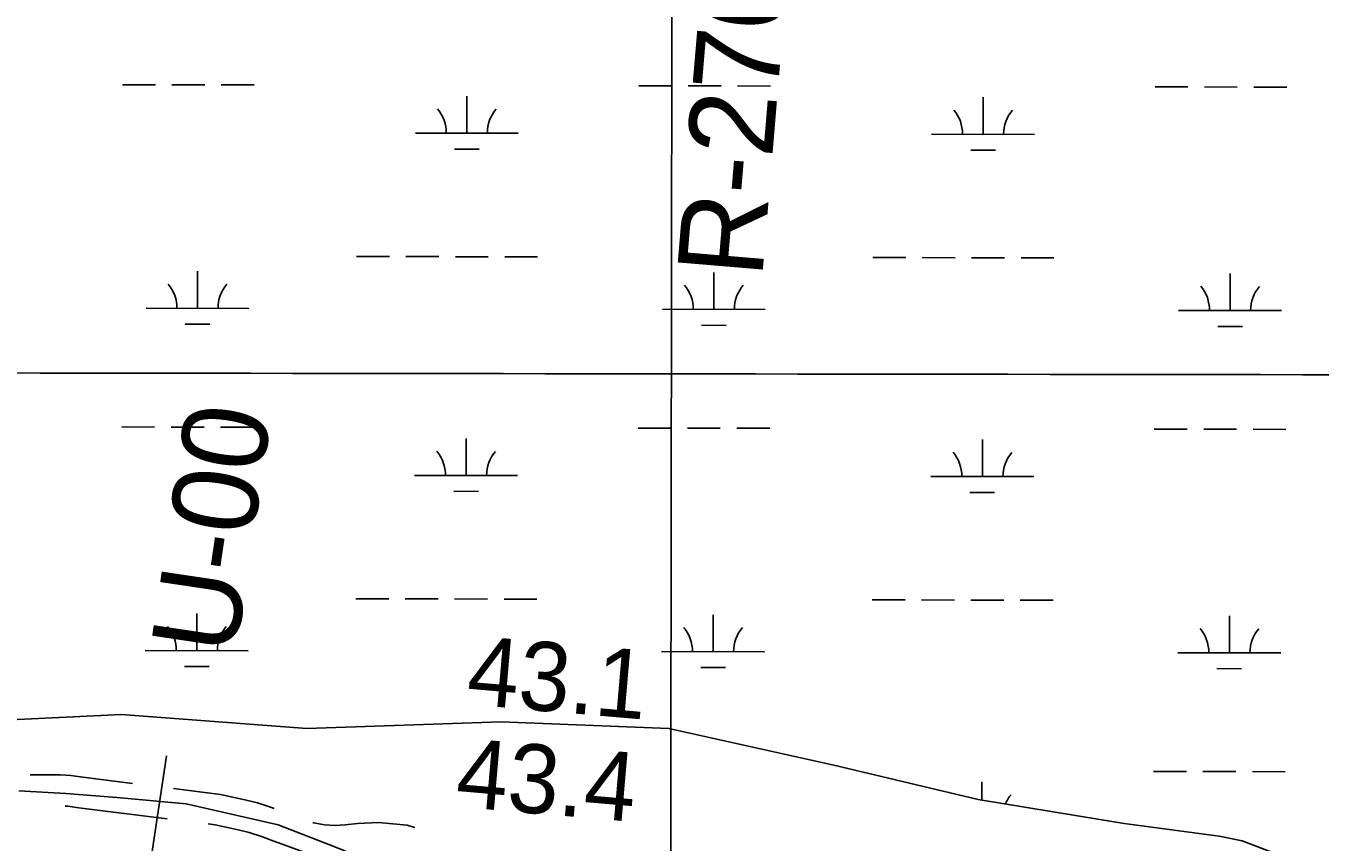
# Model space of a CAD drawing. Extents: x 3219052 to 3256913, y 800770 to 826146.
# Drawn here: x 3233083 to 3234341, y 817838 to 818631 of the extents above; entities that cross this region are included whole.
import ezdxf

# ---------------------------------------------------------------- set-up
doc = ezdxf.new("R2010")
doc.units = 0
for name, color, linetype in [('V-GRID-MAJR', 7, 'Continuous'), ('V-RIVR-RANG', 7, 'Continuous'), ('V-RIVR-RANG-IDEN', 7, 'Continuous'), ('V-ROAD-CNTR', 7, 'Continuous'), ('V-WETL-SWMP', 7, 'Continuous')]:
    doc.layers.add(name, color=color, linetype=linetype)

msp = doc.modelspace()

# ---------------------------------------------------------------- linework, layer by layer
at = {"layer": 'V-GRID-MAJR'}
for points in [[(3233694.758, 806171.2980000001), (3233702.6890000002, 812230.425), (3233710.625, 818292.637), (3233718.561, 824354.887), (3233718.565, 824357.932)], [(3223238.921, 818307.868), (3228474.772, 818299.872), (3233710.625, 818292.637), (3238946.4790000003, 818286.164), (3244182.3340000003, 818280.452), (3249418.1890000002, 818275.502), (3254654.045, 818271.314), (3254654.046, 818271.314)]]:
    msp.add_spline(points, degree=3, dxfattribs=at)
at = {"layer": 'V-RIVR-RANG'}
msp.add_line((3233219.9334, 817921.4696), (3233109.1662, 817189.8066999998), dxfattribs=at)
at = {"layer": 'V-ROAD-CNTR'}
for points in [[(3233186.928440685, 817894.5779960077), (3233138.598091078, 817900.6199709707), (3233126.7553922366, 817902.2062330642), (3233116.7853485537, 817902.7836993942), (3233107.465471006, 817902.962), (3233088.5408772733, 817902.962), (3233087.4304186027, 817902.9536902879)], [(3233076.263810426, 817887.37719786), (3233121.954719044, 817884.6432033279), (3233171.4426200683, 817880.9852106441)], [(3233324.4622326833, 817870.3409500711), (3233321.8827802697, 817871.2554452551), (3233308.3749821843, 817875.7930884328), (3233296.0248369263, 817878.684366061), (3233272.2348375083, 817883.9134939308), (3233226.6189883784, 817889.6161180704)], [(3233220.646218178, 817860.1292795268), (3233134.745908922, 817870.8680290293), (3233123.8926077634, 817872.3217669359), (3233121.4170553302, 817872.4651512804)], [(3233171.4426200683, 817880.9852106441), (3233239.0844847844, 817874.734223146), (3233328.46630602, 817854.3112639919), (3233385.2521924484, 817832.321307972), (3233435.042092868, 817811.8473489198), (3233530.56590182, 817784.111404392), (3233599.983762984, 817772.570427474), (3233839.3082843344, 817719.3975338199), (3233898.8251653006, 817713.3295459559), (3233948.552065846, 817722.858526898), (3234001.823959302, 817725.3345219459), (3234073.093816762, 817719.624533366), (3234135.356692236, 817705.770561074), (3234232.863497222, 817685.1646022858), (3234340.765281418, 817661.7506491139)], [(3233356.016185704, 817827.0294607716), (3233355.416792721, 817827.1315930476), (3233336.977398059, 817833.756292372), (3233324.1808717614, 817838.6111104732), (3233312.0932197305, 817842.8965547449), (3233300.1610178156, 817846.9049115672), (3233289.385163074, 817849.4276339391), (3233267.1431624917, 817854.3165060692), (3233260.3367564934, 817855.1674027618)], [(3233461.211996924, 817851.6729738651), (3233460.05692599, 817852.215786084), (3233453.8880851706, 817853.933947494), (3233425.877738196, 817856.5252657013), (3233419.2603250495, 817856.3603155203), (3233405.5972574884, 817855.5050652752), (3233393.499416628, 817854.2111997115), (3233383.6671431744, 817853.7703696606), (3233373.550651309, 817854.474103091), (3233363.067207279, 817856.2604069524), (3233362.037222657, 817856.630448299)]]:
    msp.add_lwpolyline(points, dxfattribs=at)
at = {"layer": 'V-WETL-SWMP'}
for p, q in [((3233177.005508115, 818573.7098373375), (3233209.0054377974, 818573.6427683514)), ((3233225.0054026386, 818573.6092338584), (3233257.0053323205, 818573.5421648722)), ((3233273.005297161, 818573.5086303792), (3233305.005226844, 818573.4415613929)), ((3233678.912405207, 818572.6578854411), (3233710.912334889, 818572.590816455)), ((3233726.91229973, 818572.5572819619), (3233758.9122294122, 818572.4902129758)), ((3233774.912194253, 818572.4566784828), (3233806.9121239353, 818572.3896094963)), ((3234180.8193022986, 818571.6059335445), (3234212.819231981, 818571.5388645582)), ((3234228.8191968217, 818571.5053300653), (3234260.819126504, 818571.4382610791)), ((3234276.8190913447, 818571.4047265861), (3234308.819021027, 818571.3376575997)), ((3233511.7514623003, 818526.5781793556), (3233511.8269126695, 818562.5780680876)), ((3234013.658359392, 818525.526227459), (3234013.7338097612, 818561.526116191)), ((3233461.7515721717, 818526.6829746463), (3233561.7513524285, 818526.4733840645)), ((3233963.6584692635, 818525.6310227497), (3234063.65824952, 818525.4214321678)), ((3233499.7191477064, 818511.1723779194), (3233523.719094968, 818511.12207618)), ((3234001.6260447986, 818510.1204260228), (3234025.6259920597, 818510.0701242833)), ((3233404.656047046, 818406.7314854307), (3233436.6559767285, 818406.6644164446)), ((3233452.6559415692, 818406.6308819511), (3233484.6558712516, 818406.5638129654)), ((3233500.6558360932, 818406.5302784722), (3233532.6557657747, 818406.463209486)), ((3233548.6557306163, 818406.429674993), (3233580.655660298, 818406.3626060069)), ((3233906.562944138, 818405.6795335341), (3233938.5628738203, 818405.6124645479)), ((3233954.5628386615, 818405.5789300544), (3233986.5627683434, 818405.5118610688)), ((3234002.562733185, 818405.4783265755), (3234034.5626628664, 818405.4112575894)), ((3234050.562627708, 818405.3777230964), (3234082.5625573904, 818405.3106541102)), ((3233249.958039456, 818356.3136525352), (3233250.033489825, 818392.313541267)), ((3233751.8649365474, 818355.2617006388), (3233751.940386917, 818391.2615893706)), ((3234253.771833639, 818354.2097487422), (3234253.847284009, 818390.2096374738)), ((3233199.9581493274, 818356.4184478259), (3233299.9579295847, 818356.2088572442)), ((3233701.865046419, 818355.3664959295), (3233801.8648266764, 818355.1569053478)), ((3234203.771943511, 818354.3145440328), (3234303.771723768, 818354.1049534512)), ((3233237.9257248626, 818340.907851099), (3233261.925672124, 818340.8575493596)), ((3233739.832621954, 818339.8558992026), (3233763.832569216, 818339.8055974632)), ((3234241.7395190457, 818338.8039473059), (3234265.7394663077, 818338.7536455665)), ((3233176.3082733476, 818241.0358655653), (3233208.30820303, 818240.9687965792)), ((3233224.3081678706, 818240.9352620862), (3233256.308097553, 818240.8681931)), ((3233272.308062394, 818240.834658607), (3233304.307992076, 818240.7675896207)), ((3233678.215170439, 818239.9839136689), (3233710.2151001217, 818239.9168446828)), ((3233726.2150649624, 818239.8833101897), (3233758.2149946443, 818239.8162412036)), ((3233774.2149594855, 818239.7827067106), (3233806.214889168, 818239.7156377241)), ((3234180.1220675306, 818238.9319617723), (3234212.1219972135, 818238.864892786)), ((3234228.121962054, 818238.8313582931), (3234260.121891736, 818238.764289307)), ((3234276.1218565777, 818238.7307548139), (3234308.1217862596, 818238.6636858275)), ((3233511.0542275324, 818193.9042075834), (3233511.1296779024, 818229.9040963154)), ((3234012.961124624, 818192.8522556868), (3234013.036574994, 818228.8521444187)), ((3233461.054337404, 818194.0090028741), (3233561.054117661, 818193.7994122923)), ((3233962.961234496, 818192.9570509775), (3234062.9610147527, 818192.7474603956)), ((3233499.021912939, 818178.4984061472), (3233523.021860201, 818178.4481044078)), ((3234000.928810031, 818177.4464542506), (3234024.9287572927, 818177.3961525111)), ((3233403.9588122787, 818074.0575136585), (3233435.958741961, 818073.9904446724)), ((3233451.9587068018, 818073.9569101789), (3233483.958636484, 818073.8898411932)), ((3233499.9586013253, 818073.8563067), (3233531.9585310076, 818073.7892377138)), ((3233547.958495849, 818073.7557032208), (3233579.958425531, 818073.6886342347)), ((3233905.8657093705, 818073.0055617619), (3233937.865639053, 818072.9384927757)), ((3233953.865603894, 818072.9049582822), (3233985.865533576, 818072.8378892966)), ((3234001.865498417, 818072.8043548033), (3234033.8654281, 818072.7372858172)), ((3234049.8653929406, 818072.7037513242), (3234081.865322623, 818072.636682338)), ((3233249.2608046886, 818023.639680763), (3233249.3362550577, 818059.6395694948)), ((3233751.1677017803, 818022.5877288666), (3233751.2431521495, 818058.5876175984)), ((3234253.074598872, 818021.53577697), (3234253.1500492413, 818057.5356657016)), ((3233199.2609145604, 818023.7444760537), (3233299.2606948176, 818023.534885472)), ((3233701.1678116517, 818022.6925241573), (3233801.167591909, 818022.4829335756)), ((3234203.0747087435, 818021.6405722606), (3234303.0744890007, 818021.430981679)), ((3233237.228490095, 818008.2338793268), (3233261.228437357, 818008.1835775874)), ((3233739.135387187, 818007.1819274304), (3233763.1353344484, 818007.131625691)), ((3234241.042284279, 818006.1299755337), (3234265.04223154, 818006.0796737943)), ((3232197.0058574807, 817915.0230226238), (3233176.2158522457, 817961.6038765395)), ((3233176.2158522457, 817961.6038765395), (3233356.1728527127, 817947.879889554)), ((3233356.1728527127, 817947.879889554), (3233545.0998518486, 817954.5818654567)), ((3233545.0998518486, 817954.5818654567), (3233708.0288518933, 817948.0478667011)), ((3233708.0288518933, 817948.0478667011), (3233868.6878538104, 817912.3779202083)), ((3233868.6878538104, 817912.377920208), (3234008.78985564, 817878.8169712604)), ((3234179.4248327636, 817906.2579900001), (3234211.424762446, 817906.1909210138)), ((3234227.4247272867, 817906.1573865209), (3234259.424656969, 817906.0903175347)), ((3234275.42462181, 817906.0567830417), (3234307.424551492, 817905.9897140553)), ((3234012.3017461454, 817878.2407820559), (3234012.3393402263, 817896.1781726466)), ((3234008.78985564, 817878.8169712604), (3234150.8038568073, 817855.5170038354)), ((3234150.8038568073, 817855.5170038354), (3234243.2578573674, 817843.4590194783)), ((3234243.2578573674, 817843.4590194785), (3234265.585857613, 817838.8310263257)), ((3234265.585857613, 817838.8310263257), (3234730.7998760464, 817660.9375407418))]:
    msp.add_line(p, q, dxfattribs=at)
for centre, radius, start, end in [((3233456.509642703, 818527.1687650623), 35.24628790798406, 359.1080939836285, 40.65175231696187), ((3233566.995272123, 818526.9371970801), 35.246287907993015, 139.10808960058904, 180.65174793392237), ((3233958.4165397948, 818526.1168131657), 35.24628790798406, 359.1080939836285, 40.65175231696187), ((3234068.9021692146, 818525.8852451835), 35.246287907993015, 139.10808960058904, 180.65174793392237), ((3233194.716219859, 818356.904238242), 35.24628790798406, 359.1080939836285, 40.65175231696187), ((3233305.201849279, 818356.6726702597), 35.246287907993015, 139.10808960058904, 180.65174793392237), ((3233696.623116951, 818355.8522863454), 35.24628790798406, 359.1080939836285, 40.65175231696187), ((3233807.1087463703, 818355.6207183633), 35.246287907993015, 139.10808960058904, 180.65174793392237), ((3234198.5300140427, 818354.8003344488), 35.24628790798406, 359.1080939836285, 40.65175231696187), ((3234309.015643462, 818354.5687664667), 35.246287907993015, 139.10808960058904, 180.65174793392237), ((3233455.812407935, 818194.4947932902), 35.24628790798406, 359.1080939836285, 40.65175231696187), ((3233566.2980373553, 818194.2632253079), 35.246287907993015, 139.10808960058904, 180.65174793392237), ((3233957.7193050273, 818193.4428413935), 35.24628790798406, 359.1080939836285, 40.65175231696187), ((3234068.2049344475, 818193.2112734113), 35.246287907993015, 139.10808960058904, 180.65174793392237), ((3233194.018985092, 818024.2302664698), 35.24628790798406, 359.1080939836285, 40.65175231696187), ((3233304.5046145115, 818023.9986984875), 35.246287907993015, 139.10808960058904, 180.65174793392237), ((3233695.9258821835, 818023.1783145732), 35.24628790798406, 359.1080939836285, 40.65175231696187), ((3233806.4115116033, 818022.9467465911), 35.246287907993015, 139.10808960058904, 180.65174793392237), ((3234197.8327792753, 818022.1263626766), 35.24628790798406, 359.1080939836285, 40.65175231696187), ((3234308.3184086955, 818021.8947946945), 35.246287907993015, 139.10808960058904, 180.65174793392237), ((3234067.50769968, 817860.5373016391), 35.246287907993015, 139.10808960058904, 156.67415908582)]:
    msp.add_arc(centre, radius, start, end, dxfattribs=at)

# ---------------------------------------------------------------- texts
at = {"layer": 'V-RIVR-RANG'}
for s, p in [('43.1', (3233510.4839606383, 817971.6043657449)), ('43.4', (3233499.7747336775, 817872.1574544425))]:
    msp.add_text(s, height=67, rotation=355.06832571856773, dxfattribs=at).set_placement(p)
at = {"layer": 'V-RIVR-RANG-IDEN'}
for s, rotation, p in [('R-270.2', 85.21374023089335, (3233798.8075619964, 818384.9526286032)), ('U-00', 81.52423934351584, (3233286.761833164, 818017.4289690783))]:
    msp.add_text(s, height=82.99999799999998, rotation=rotation, dxfattribs=at).set_placement(p)

doc.saveas('drawing.dxf')
